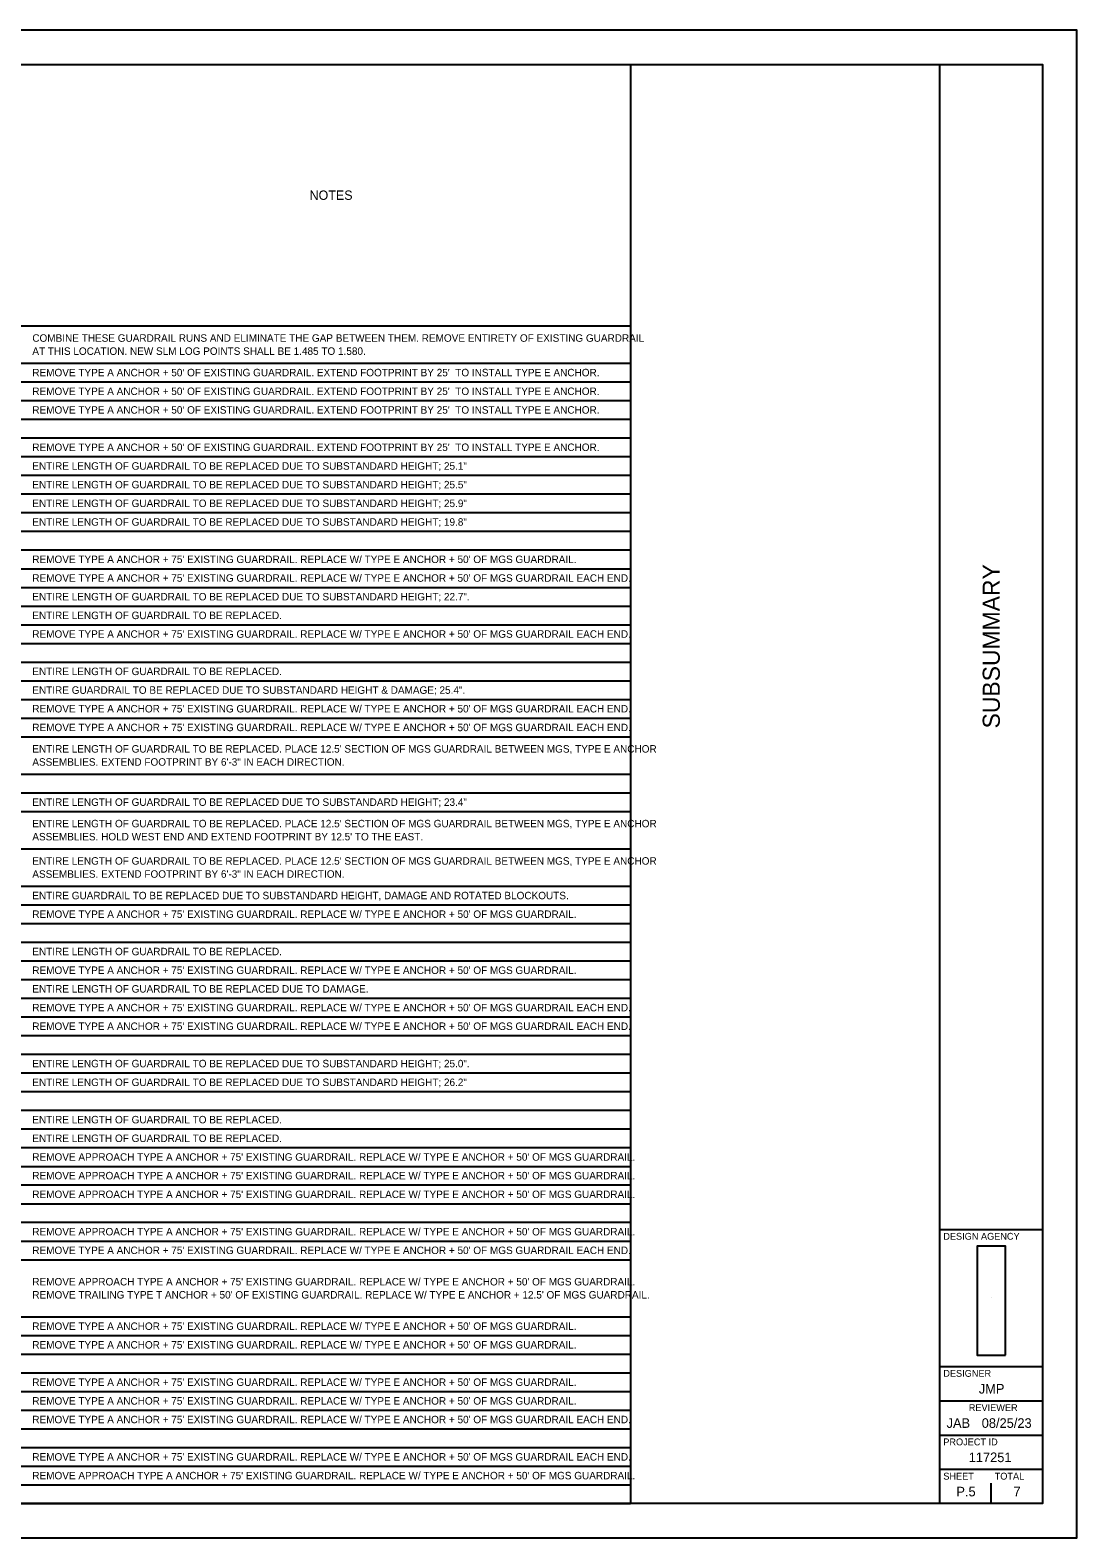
# Model space of a CAD drawing. Extents: x 0 to 34, y 0 to 22.
# Drawn here: x 18.72 to 34, y 0 to 22 of the extents above; entities that cross this region are included whole.
import ezdxf

# ---------------------------------------------------------------- set-up
doc = ezdxf.new("R2010")
doc.units = 0
for name, color, linetype in [('SH_Border', 7, 'Continuous'), ('SH_Cut_Line', 7, 'Continuous'), ('SH_Data', 7, 'Continuous'), ('SH_Text', 7, 'Continuous')]:
    doc.layers.add(name, color=color, linetype=linetype)

msp = doc.modelspace()

# ---------------------------------------------------------------- linework, layer by layer
at = {"layer": 'SH_Border'}
for p, q in [((32, 0.5), (32, 21.5)), ((32, 4.5), (33.5, 4.5)), ((32, 2.5), (33.5, 2.5)), ((32, 2), (33.5, 2)), ((32, 1.5), (33.5, 1.5)), ((32, 1), (33.5, 1))]:
    msp.add_line(p, q, dxfattribs=at)
msp.add_lwpolyline([(1.5, 21.5), (33.5, 21.5), (33.5, 0.5), (1.5, 0.5)], close=True, dxfattribs=at)
at = {"layer": 'SH_Cut_Line'}
msp.add_lwpolyline([(0, 0), (34, 0), (34, 22), (0, 22)], close=True, dxfattribs=at)
at = {"layer": 'SH_Data'}
for p, q in [((32.75, 3.5), (32.75, 3.5)), ((32.375, 0.675), (32.375, 0.675)), ((32.75, 0.5), (32.75, 0.8))]:
    msp.add_line(p, q, dxfattribs=at)
at = {"layer": 'SH_Text'}
for p, q in [((1.5, 21.5), (27.485, 21.5)), ((27.485, 21.5), (27.485, 0.5)), ((1.5, 17.685), (27.485, 17.685)), ((1.5, 17.14), (27.485, 17.14)), ((1.5, 16.867), (27.485, 16.867)), ((1.5, 16.595), (27.485, 16.595)), ((1.5, 16.322), (27.485, 16.322)), ((1.5, 16.05), (27.485, 16.05)), ((1.5, 15.777), (27.485, 15.777)), ((1.5, 15.505), (27.485, 15.505)), ((1.5, 15.232), (27.485, 15.232)), ((1.5, 14.96), (27.485, 14.96)), ((1.5, 14.687), (27.485, 14.687)), ((1.5, 14.415), (27.485, 14.415)), ((1.5, 14.142), (27.485, 14.142)), ((1.5, 13.869), (27.485, 13.869)), ((1.5, 13.597), (27.485, 13.597)), ((1.5, 13.324), (27.485, 13.324)), ((1.5, 13.052), (27.485, 13.052)), ((1.5, 12.779), (27.485, 12.779)), ((1.5, 12.507), (27.485, 12.507)), ((1.5, 12.234), (27.485, 12.234)), ((1.5, 11.962), (27.485, 11.962)), ((1.5, 11.689), (27.485, 11.689)), ((1.5, 11.144), (27.485, 11.144)), ((1.5, 10.872), (27.485, 10.872)), ((1.5, 10.599), (27.485, 10.599)), ((1.5, 10.054), (27.485, 10.054)), ((1.5, 9.509), (27.485, 9.509)), ((1.5, 9.237), (27.485, 9.237)), ((1.5, 8.964), (27.485, 8.964)), ((1.5, 8.692), (27.485, 8.692)), ((1.5, 8.419), (27.485, 8.419)), ((1.5, 8.147), (27.485, 8.147)), ((1.5, 7.874), (27.485, 7.874)), ((1.5, 7.602), (27.485, 7.602)), ((1.5, 7.329), (27.485, 7.329)), ((1.5, 7.056), (27.485, 7.056)), ((1.5, 6.784), (27.485, 6.784)), ((1.5, 6.511), (27.485, 6.511)), ((1.5, 6.239), (27.485, 6.239)), ((1.5, 5.966), (27.485, 5.966)), ((1.5, 5.694), (27.485, 5.694)), ((1.5, 5.421), (27.485, 5.421)), ((1.5, 5.149), (27.485, 5.149)), ((1.5, 4.876), (27.485, 4.876)), ((1.5, 4.604), (27.485, 4.604)), ((1.5, 4.331), (27.485, 4.331)), ((1.5, 4.059), (27.485, 4.059)), ((1.5, 3.225), (27.485, 3.225)), ((1.5, 2.953), (27.485, 2.953)), ((1.5, 2.68), (27.485, 2.68)), ((1.5, 2.408), (27.485, 2.408)), ((1.5, 2.135), (27.485, 2.135)), ((1.5, 1.863), (27.485, 1.863)), ((1.5, 1.59), (27.485, 1.59)), ((1.5, 1.318), (27.485, 1.318)), ((1.5, 1.045), (27.485, 1.045)), ((1.5, 0.773), (27.485, 0.773)), ((1.5, 0.5), (27.485, 0.5))]:
    msp.add_line(p, q, dxfattribs=at)
msp.add_lwpolyline([(32.956, 2.664), (32.956, 4.254), (32.544, 4.254), (32.544, 2.664)], close=True, dxfattribs=at)

# ---------------------------------------------------------------- texts
at = {"layer": 'SH_Data'}
msp.add_text('SUBSUMMARY', height=0.25, rotation=90, dxfattribs=at).set_placement((32.875, 11.811))
for s, height, p in [('DESIGN AGENCY', 0.1, (32.05, 4.35)), ('DESIGNER', 0.1, (32.05, 2.35)), ('JMP', 0.14, (32.568, 2.105)), ('REVIEWER', 0.1, (32.422, 1.85)), ('JAB', 0.14, (32.098, 1.605)), ('08/25/23', 0.14, (32.611, 1.605)), ('PROJECT ID', 0.1, (32.05, 1.35)), ('117251', 0.14, (32.421, 1.105)), ('SHEET', 0.1, (32.05, 0.85)), ('TOTAL', 0.1, (32.8, 0.85)), ('P.5', 0.14, (32.241, 0.605)), ('7', 0.14, (33.074, 0.605))]:
    msp.add_text(s, height=height, dxfattribs=at).set_placement(p)
at = {"layer": 'SH_Text'}
for s, height, p in [('NOTES', 0.1363, (22.797, 19.524)), ('COMBINE THESE GUARDRAIL RUNS AND ELIMINATE THE GAP BETWEEN THEM. REMOVE ENTIRETY OF EXISTING GUARDRAIL ', 0.109008, (18.749, 17.453)), ('AT THIS LOCATION. NEW SLM LOG POINTS SHALL BE 1.485 TO 1.580.', 0.10901, (18.749, 17.262)), ("REMOVE TYPE A ANCHOR + 50' OF EXISTING GUARDRAIL. EXTEND FOOTPRINT BY 25'  TO INSTALL TYPE E ANCHOR.", 0.10901, (18.749, 16.949)), ("REMOVE TYPE A ANCHOR + 50' OF EXISTING GUARDRAIL. EXTEND FOOTPRINT BY 25'  TO INSTALL TYPE E ANCHOR.", 0.10901, (18.749, 16.676)), ("REMOVE TYPE A ANCHOR + 50' OF EXISTING GUARDRAIL. EXTEND FOOTPRINT BY 25'  TO INSTALL TYPE E ANCHOR.", 0.10901, (18.749, 16.404)), ("REMOVE TYPE A ANCHOR + 50' OF EXISTING GUARDRAIL. EXTEND FOOTPRINT BY 25'  TO INSTALL TYPE E ANCHOR.", 0.10901, (18.749, 15.859)), ('ENTIRE LENGTH OF GUARDRAIL TO BE REPLACED DUE TO SUBSTANDARD HEIGHT; 25.1"', 0.10901, (18.749, 15.586)), ('ENTIRE LENGTH OF GUARDRAIL TO BE REPLACED DUE TO SUBSTANDARD HEIGHT; 25.5"', 0.10901, (18.749, 15.314)), ('ENTIRE LENGTH OF GUARDRAIL TO BE REPLACED DUE TO SUBSTANDARD HEIGHT; 25.9"', 0.10901, (18.749, 15.041)), ('ENTIRE LENGTH OF GUARDRAIL TO BE REPLACED DUE TO SUBSTANDARD HEIGHT; 19.8"', 0.10901, (18.749, 14.769)), ("REMOVE TYPE A ANCHOR + 75' EXISTING GUARDRAIL. REPLACE W/ TYPE E ANCHOR + 50' OF MGS GUARDRAIL.", 0.10901, (18.749, 14.224)), ("REMOVE TYPE A ANCHOR + 75' EXISTING GUARDRAIL. REPLACE W/ TYPE E ANCHOR + 50' OF MGS GUARDRAIL EACH END.", 0.109008, (18.749, 13.951)), ('ENTIRE LENGTH OF GUARDRAIL TO BE REPLACED DUE TO SUBSTANDARD HEIGHT; 22.7".', 0.10901, (18.749, 13.679)), ('ENTIRE LENGTH OF GUARDRAIL TO BE REPLACED.', 0.10901, (18.749, 13.406)), ("REMOVE TYPE A ANCHOR + 75' EXISTING GUARDRAIL. REPLACE W/ TYPE E ANCHOR + 50' OF MGS GUARDRAIL EACH END.", 0.109008, (18.749, 13.134)), ('ENTIRE LENGTH OF GUARDRAIL TO BE REPLACED.', 0.10901, (18.749, 12.589)), ('ENTIRE GUARDRAIL TO BE REPLACED DUE TO SUBSTANDARD HEIGHT & DAMAGE; 25.4".', 0.10901, (18.749, 12.316)), ("REMOVE TYPE A ANCHOR + 75' EXISTING GUARDRAIL. REPLACE W/ TYPE E ANCHOR + 50' OF MGS GUARDRAIL EACH END.", 0.109008, (18.749, 12.044)), ("REMOVE TYPE A ANCHOR + 75' EXISTING GUARDRAIL. REPLACE W/ TYPE E ANCHOR + 50' OF MGS GUARDRAIL EACH END.", 0.109008, (18.749, 11.771)), ("ENTIRE LENGTH OF GUARDRAIL TO BE REPLACED. PLACE 12.5' SECTION OF MGS GUARDRAIL BETWEEN MGS, TYPE E ANCHOR ", 0.109008, (18.749, 11.458)), ('ASSEMBLIES. EXTEND FOOTPRINT BY 6\'-3" IN EACH DIRECTION.', 0.10901, (18.749, 11.267)), ('ENTIRE LENGTH OF GUARDRAIL TO BE REPLACED DUE TO SUBSTANDARD HEIGHT; 23.4"', 0.10901, (18.749, 10.681)), ("ENTIRE LENGTH OF GUARDRAIL TO BE REPLACED. PLACE 12.5' SECTION OF MGS GUARDRAIL BETWEEN MGS, TYPE E ANCHOR ", 0.109008, (18.749, 10.368)), ("ASSEMBLIES. HOLD WEST END AND EXTEND FOOTPRINT BY 12.5' TO THE EAST.", 0.10901, (18.749, 10.177)), ("ENTIRE LENGTH OF GUARDRAIL TO BE REPLACED. PLACE 12.5' SECTION OF MGS GUARDRAIL BETWEEN MGS, TYPE E ANCHOR ", 0.109008, (18.749, 9.823)), ('ASSEMBLIES. EXTEND FOOTPRINT BY 6\'-3" IN EACH DIRECTION.', 0.10901, (18.749, 9.632)), ('ENTIRE GUARDRAIL TO BE REPLACED DUE TO SUBSTANDARD HEIGHT, DAMAGE AND ROTATED BLOCKOUTS.', 0.10901, (18.749, 9.318)), ("REMOVE TYPE A ANCHOR + 75' EXISTING GUARDRAIL. REPLACE W/ TYPE E ANCHOR + 50' OF MGS GUARDRAIL.", 0.10901, (18.749, 9.046)), ('ENTIRE LENGTH OF GUARDRAIL TO BE REPLACED.', 0.10901, (18.749, 8.501)), ("REMOVE TYPE A ANCHOR + 75' EXISTING GUARDRAIL. REPLACE W/ TYPE E ANCHOR + 50' OF MGS GUARDRAIL.", 0.10901, (18.749, 8.228)), ('ENTIRE LENGTH OF GUARDRAIL TO BE REPLACED DUE TO DAMAGE.', 0.10901, (18.749, 7.956)), ("REMOVE TYPE A ANCHOR + 75' EXISTING GUARDRAIL. REPLACE W/ TYPE E ANCHOR + 50' OF MGS GUARDRAIL EACH END.", 0.109008, (18.749, 7.683)), ("REMOVE TYPE A ANCHOR + 75' EXISTING GUARDRAIL. REPLACE W/ TYPE E ANCHOR + 50' OF MGS GUARDRAIL EACH END.", 0.109008, (18.749, 7.411)), ('ENTIRE LENGTH OF GUARDRAIL TO BE REPLACED DUE TO SUBSTANDARD HEIGHT; 25.0".', 0.10901, (18.749, 6.866)), ('ENTIRE LENGTH OF GUARDRAIL TO BE REPLACED DUE TO SUBSTANDARD HEIGHT; 26.2"', 0.10901, (18.749, 6.593)), ('ENTIRE LENGTH OF GUARDRAIL TO BE REPLACED.', 0.10901, (18.749, 6.048)), ('ENTIRE LENGTH OF GUARDRAIL TO BE REPLACED.', 0.10901, (18.749, 5.776)), ("REMOVE APPROACH TYPE A ANCHOR + 75' EXISTING GUARDRAIL. REPLACE W/ TYPE E ANCHOR + 50' OF MGS GUARDRAIL.", 0.109008, (18.749, 5.503)), ("REMOVE APPROACH TYPE A ANCHOR + 75' EXISTING GUARDRAIL. REPLACE W/ TYPE E ANCHOR + 50' OF MGS GUARDRAIL.", 0.109008, (18.749, 5.231)), ("REMOVE APPROACH TYPE A ANCHOR + 75' EXISTING GUARDRAIL. REPLACE W/ TYPE E ANCHOR + 50' OF MGS GUARDRAIL.", 0.109008, (18.749, 4.958)), ("REMOVE APPROACH TYPE A ANCHOR + 75' EXISTING GUARDRAIL. REPLACE W/ TYPE E ANCHOR + 50' OF MGS GUARDRAIL.", 0.109008, (18.749, 4.413)), ("REMOVE TYPE A ANCHOR + 75' EXISTING GUARDRAIL. REPLACE W/ TYPE E ANCHOR + 50' OF MGS GUARDRAIL EACH END.", 0.109008, (18.749, 4.141)), ("REMOVE APPROACH TYPE A ANCHOR + 75' EXISTING GUARDRAIL. REPLACE W/ TYPE E ANCHOR + 50' OF MGS GUARDRAIL. ", 0.109008, (18.749, 3.683)), ("REMOVE TRAILING TYPE T ANCHOR + 50' OF EXISTING GUARDRAIL. REPLACE W/ TYPE E ANCHOR + 12.5' OF MGS GUARDRAIL.", 0.109008, (18.749, 3.492)), ("REMOVE TYPE A ANCHOR + 75' EXISTING GUARDRAIL. REPLACE W/ TYPE E ANCHOR + 50' OF MGS GUARDRAIL.", 0.10901, (18.749, 3.034)), ("REMOVE TYPE A ANCHOR + 75' EXISTING GUARDRAIL. REPLACE W/ TYPE E ANCHOR + 50' OF MGS GUARDRAIL.", 0.10901, (18.749, 2.762)), ("REMOVE TYPE A ANCHOR + 75' EXISTING GUARDRAIL. REPLACE W/ TYPE E ANCHOR + 50' OF MGS GUARDRAIL.", 0.10901, (18.749, 2.217)), ("REMOVE TYPE A ANCHOR + 75' EXISTING GUARDRAIL. REPLACE W/ TYPE E ANCHOR + 50' OF MGS GUARDRAIL.", 0.10901, (18.749, 1.944)), ("REMOVE TYPE A ANCHOR + 75' EXISTING GUARDRAIL. REPLACE W/ TYPE E ANCHOR + 50' OF MGS GUARDRAIL EACH END.", 0.109008, (18.749, 1.672)), ("REMOVE TYPE A ANCHOR + 75' EXISTING GUARDRAIL. REPLACE W/ TYPE E ANCHOR + 50' OF MGS GUARDRAIL EACH END.", 0.109008, (18.749, 1.127)), ("REMOVE APPROACH TYPE A ANCHOR + 75' EXISTING GUARDRAIL. REPLACE W/ TYPE E ANCHOR + 50' OF MGS GUARDRAIL.", 0.109008, (18.749, 0.854))]:
    msp.add_text(s, height=height, dxfattribs=at).set_placement(p)

doc.saveas('drawing.dxf')
